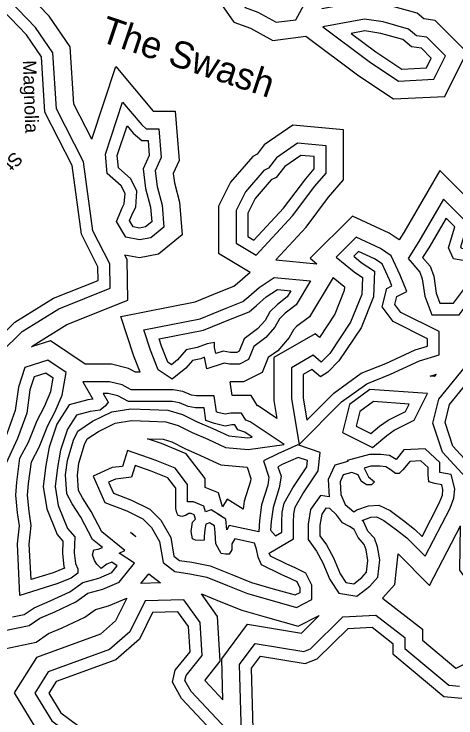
# Model space of a CAD drawing. Extents: x 2104537 to 2336408, y 34176 to 229611.
# Drawn here: x 2191069 to 2193537, y 61547 to 65482 of the extents above; entities that cross this region are included whole.
import ezdxf

# ---------------------------------------------------------------- set-up
doc = ezdxf.new("R2010")
doc.units = 0
for name, color, linetype in [('Exist Hydrographic Buffer Line', 7, 'Continuous'), ('Exist Hydrographic Island Shore', 7, 'Continuous'), ('Exist Hydrographic River Shore', 7, 'Continuous'), ('Exist Road Non-System Type 51 Label', 7, 'Continuous'), ('Old_Level_32', 7, 'Continuous')]:
    doc.layers.add(name, color=color, linetype=linetype)

msp = doc.modelspace()

# ---------------------------------------------------------------- linework, layer by layer
at = {"layer": 'Exist Hydrographic Buffer Line'}
for points in [[(2192286.8, 65662.8), (2192272, 65644.4), (2192360, 65518.6), (2192429.9, 65492.4), (2192533.9, 65436.4), (2192643.1, 65450), (2192701.1, 65556.3), (2192744.4, 65643.1), (2192694.7, 65734.2), (2192694.7, 65767.9), (2192719.5, 65836), (2192736.2, 65902.8), (2192651.7, 65987.3), (2192581.5, 66013.7), (2192494, 66040.6), (2192429.4, 66069.4), (2192355.9, 66085.1), (2192334.1, 66125.1), (2192323.3, 66184.6), (2192323.3, 66189.3), (2192364.5, 66223.7), (2192364.5, 66319.1), (2192268.3, 66376.9), (2192157.7, 66469.1)], [(2190989.7, 63585.2), (2191114.3, 63707.3), (2191319.4, 63834.1), (2191604.9, 63949), (2191603, 64084.7), (2191508.3, 64270.6), (2191456.2, 64655.5), (2191305.3, 64951.5), (2191286, 65264.7), (2191188.9, 65407.1), (2191039.9, 65563.1), (2190793.9, 65645.6), (2190364.1, 65611.5), (2190190, 65689.2), (2190098.8, 65777.5), (2189893.2, 65745.3), (2189917, 65845), (2189904, 65986.7), (2189704.4, 66111.5)], [(2191502.4, 64781.6), (2191402.3, 64978), (2191382.6, 65297.8), (2191265.7, 65469.2), (2191094.3, 65648.7), (2190806.1, 65745.3), (2190381.3, 65711.6), (2190246, 65772), (2190132, 65882.3), (2190014.1, 65863.9), (2189998, 66040)], [(2192149.7, 65649), (2192149.2, 65648.3), (2192296.8, 65437.2), (2192389.1, 65402.6), (2192514.9, 65334.8), (2192699.6, 65357.9)], [(2192699.6, 65357.9), (2192995.2, 65136.1), (2193188.5, 65007.1), (2193476, 65021.5), (2193599.1, 65268), (2193420.8, 65446.5), (2193358.9, 65454.2), (2193320.5, 65487.2), (2193152.1, 65534), (2193025.9, 65553.4), (2192788, 65510.1)], [(2192792.9, 65411), (2193052.1, 65216.5), (2193216.1, 65107), (2193413.6, 65116.9), (2193479.4, 65248.6), (2193375.1, 65353), (2193317.3, 65360.2), (2193273, 65398.2), (2193131.4, 65437.6), (2193027.2, 65453.6), (2192792.9, 65411)], [(2191502.4, 64781.6), (2191637.9, 65188.4)], [(2191637.9, 65188.4), (2191846.1, 64938.4), (2191968.3, 64938.4), (2191991.3, 64662.8), (2191958.4, 64590.4), (2191965, 64537.3), (2191993.4, 64430.8), (2192008.7, 64246.6), (2191875, 64139.5), (2191769.2, 64118.3), (2191688.1, 64134.6)], [(2191675.4, 64989.6), (2191781.7, 64861.9), (2191807.3, 64840), (2191877.8, 64840), (2191891.1, 64680.2), (2191857.3, 64605.8), (2191868.2, 64518.5), (2191896, 64413.9), (2191906.3, 64290.7), (2191832.2, 64231.3), (2191769.2, 64218.7), (2191693.5, 64233.9), (2191640.7, 64321.9), (2191675.3, 64402.7), (2191684.1, 64420.5), (2191688.6, 64479.1), (2191667.9, 64520.5), (2191589.5, 64591.2), (2191578.7, 64699.2), (2191675.4, 64989.6)], [(2192530.8, 64106.9), (2192700.3, 64290.7), (2192825.5, 64457.7), (2192910.1, 64554.5), (2192910.1, 64834.7), (2192625.9, 64860.5), (2192466.9, 64750.3), (2192426.1, 64697.9), (2192402.7, 64686.2), (2192278.3, 64542.6), (2192210.5, 64406.9), (2192210.5, 64144.6), (2192387, 64038.7)], [(2192421, 64133), (2192624.6, 64353.7), (2192748.9, 64519.7), (2192811.7, 64591.4), (2192811.7, 64744.8), (2192652.6, 64759.3), (2192535.3, 64678), (2192490.1, 64619.9), (2192464.2, 64606.9), (2192360.9, 64487.6), (2192309, 64383.7), (2192309, 64200.3), (2192421, 64133)], [(2193447.7, 64607.3), (2193245.4, 64260.3), (2193219.9, 64219.5)], [(2194159.6, 64601.1), (2193777.8, 64601.1), (2193668.6, 64431.2), (2193650.4, 64404.4), (2193447.7, 64607.3)], [(2193468.3, 64447.3), (2193329.6, 64209.4), (2193270.3, 64114.3), (2193335.3, 64038.3), (2193349.4, 64000.8), (2193363.2, 63904.4), (2193402.3, 63800.1), (2193556.2, 63800.1), (2193628.5, 63896.6), (2193698.6, 63931.6), (2193785.8, 64058.5), (2193953.1, 64365.4), (2194021.7, 64502.7), (2193831.5, 64502.7), (2193750.7, 64376.9), (2193654.2, 64235.2), (2193629.2, 64216.5), (2193596, 64176.6), (2193584.7, 64169.1), (2193569.3, 64171.9), (2193565.6, 64180.1), (2193604.2, 64311.4), (2193468.3, 64447.3)], [(2193219.9, 64219.5), (2193163.5, 64257.1), (2192958.6, 64351.7), (2192723.3, 64116.3), (2192759.4, 64086.2)], [(2192661, 63075.1), (2192898.9, 63313.1), (2193039.5, 63415.4), (2193170.9, 63468.1), (2193333.4, 63542.6), (2193444.6, 63575.9), (2193444.6, 63706.6), (2193229.6, 63814.2), (2193196, 63858.9), (2193207.7, 63902.9), (2193262.8, 63930.4), (2193226, 64022.4), (2193176.2, 64130.3), (2193115.3, 64170.9), (2192979.7, 64233.6), (2192869, 64122.9), (2192968.7, 64039.8), (2193015.8, 64009.8), (2193011.2, 63914.2), (2192949.1, 63758.7), (2192832.6, 63583.9), (2192784.4, 63535.7), (2192739.9, 63573.9), (2192618.5, 63504.5), (2192618.5, 63330.2), (2192661, 63075.1)], [(2191166.7, 63620.9), (2191175.4, 63629.3), (2191364, 63746), (2191704.2, 63882.9), (2191701.1, 64109), (2191688.1, 64134.6)], [(2192530.8, 64106.9), (2192759.4, 64086.2)], [(2191664.6, 63791.4), (2192079.7, 63872.2), (2192216.7, 63928.3), (2192296.4, 63960.1), (2192316.2, 63976.7), (2192387, 64038.7)], [(2191793.4, 63716.2), (2192108.1, 63777.4), (2192253.7, 63837), (2192347.4, 63874.6), (2192380.1, 63901.8), (2192437.8, 63952.3), (2192522.6, 64008.9), (2192725.4, 63990.4), (2192644.4, 63855.4), (2192582.8, 63809.1), (2192551, 63777.3), (2192524.8, 63731.4), (2192474.5, 63672.6), (2192407.9, 63624.1), (2192378.1, 63549.7), (2192328.2, 63524.7), (2192272.8, 63524.7), (2192242.3, 63529.8), (2192146, 63497.7), (2192132.9, 63562.9), (2192111.3, 63554.8), (2192065.9, 63544.7), (2192028, 63501.5), (2191951.6, 63440.3), (2191873.7, 63492.3), (2191831.3, 63602.6), (2191793.4, 63716.2)], [(2192851.5, 64009.4), (2192718.9, 63788.2), (2192647.5, 63734.6), (2192630, 63717.1), (2192605.6, 63674.4), (2192541.7, 63599.8), (2192488.7, 63561.3), (2192455.6, 63478.4), (2192351.4, 63426.3), (2192275.4, 63426.3)], [(2192851.5, 64009.4), (2192910.5, 63960.2), (2192914.8, 63957.4), (2192913.7, 63935.4), (2192861.5, 63804.8), (2192774.4, 63674), (2192751.3, 63693.8), (2192520.1, 63561.6), (2192520.1, 63322.1), (2192536.9, 63221)], [(2191773.1, 63479.7), (2191738.6, 63569.4), (2191664.6, 63791.4)], [(2193614.6, 62866.2), (2193461.7, 63031.8), (2193408.6, 63195.4), (2193441.6, 63329.1), (2193810.1, 63781.6)], [(2191272, 63654.1), (2191166.7, 63620.9)], [(2191466.4, 63524.5), (2191272, 63654.1)], [(2191256.6, 63546), (2191129.4, 63505.8), (2191092.7, 63395.8), (2191075.7, 63266), (2191027.5, 63134.2), (2190959.8, 62988.1), (2190940.2, 62882.1), (2190936.6, 62759), (2190936.6, 62633.3), (2190940.1, 62489), (2190953.9, 62350.7), (2190957.2, 62272.6), (2190953.1, 62167), (2191027.4, 62036.9), (2191152.4, 62063.2), (2191212.8, 62104.8), (2191297.2, 62140.5), (2191413.8, 62195.2), (2191481.3, 62243.4), (2191563.8, 62265.7), (2191655.1, 62304.8), (2191742, 62411.1), (2191656, 62468.5)], [(2191656, 62468.5), (2191688.4, 62482.4), (2191559.6, 62587.1), (2191499.3, 62701.5), (2191450.6, 62778), (2191427.9, 62818.5), (2191422.4, 62903.9), (2191431.2, 62971.4), (2191462.6, 63075.3), (2191477, 63106.1), (2191540.5, 63148.4), (2191634.4, 63193.9), (2191725.3, 63208.6), (2191825.5, 63205.3), (2191917, 63202.2), (2191985.9, 63182.1), (2192064.6, 63142.7), (2192151.6, 63104.4), (2192250.6, 63058.7), (2192376.1, 63046.5), (2192577.9, 63075.4), (2192387.2, 63202.5), (2192363.2, 63211.3), (2192338.7, 63250.5), (2192279.2, 63250.5), (2192249, 63245), (2192207.5, 63254.8), (2192200.1, 63257.4), (2192187.3, 63346.9), (2192087.7, 63346.9), (2192059.5, 63351.6), (2192011.4, 63372.2), (2191957, 63381.3), (2191910.2, 63381.3), (2191862.1, 63381.3), (2191723.6, 63381.3), (2191672.5, 63408.4), (2191601.9, 63426), (2191453.3, 63426), (2191508.9, 63328.6), (2191481.3, 63325.1), (2191377, 63296.7), (2191307, 63189.3), (2191265.1, 63059.7), (2191246.9, 62957.3), (2191231.7, 62839.6), (2191251.6, 62716.2), (2191310, 62572.1), (2191341.5, 62535.3), (2191338.9, 62466.3), (2191347.5, 62392.9), (2191351.4, 62384.2), (2191286.4, 62358.7), (2191163.4, 62319.8), (2191154, 62518.7), (2191164.6, 62621.7), (2191153.3, 62700.7), (2191143.8, 62792.8), (2191150, 62857.5), (2191165.5, 62978.6), (2191209.6, 63060.7), (2191258, 63181.6), (2191299, 63260.3), (2191337.2, 63352), (2191359.9, 63477.1), (2191256.6, 63546)], [(2191773.1, 63479.7), (2191748.1, 63479.7), (2191708, 63500.9), (2191614, 63524.5), (2191466.4, 63524.5)], [(2191014.1, 63471.4), (2190996.4, 63418), (2190979.5, 63289.6), (2190936.5, 63171.9), (2190865.3, 63018.2), (2190842, 62892.5), (2190838.1, 62760.5), (2190838.1, 62632.2), (2190841.8, 62482.9), (2190855.7, 62343.8), (2190858.7, 62272.5), (2190853.7, 62142.7), (2190977.5, 61925.8), (2191192, 61971), (2191260.3, 62018), (2191337.3, 62050.6), (2191463.8, 62109.9), (2191524.1, 62153), (2191596.1, 62172.5), (2191699.2, 62216.7)], [(2193392.6, 63457.6), (2193428, 63468.2)], [(2193417.9, 63455.8), (2193392.6, 63457.6)], [(2193417.9, 63455.8), (2193428, 63468.2)], [(2192536.9, 63221), (2192432, 63291), (2192428.8, 63292.2), (2192393.3, 63348.9), (2192286.4, 63348.9), (2192275.4, 63426.3)], [(2193072.1, 63057.8), (2193151.2, 63125.6), (2193192.8, 63155.3), (2193304, 63211), (2193378.4, 63359.9), (2193057, 63382.1), (2192942.7, 63298.9), (2192903.5, 63142.2), (2193072.1, 63057.8)], [(2192233.4, 62726.3), (2192211, 62804.7), (2192136.2, 62834.7), (2192136.2, 62885.8), (2192030.7, 63023.9), (2191892.4, 63080.3), (2191814.6, 63107.2)], [(2191814.6, 63107.2), (2191901.2, 63104.2), (2191949.8, 63090.1), (2192022.7, 63053.6), (2192111.1, 63014.7), (2192224.4, 62962.3), (2192371.1, 62948.1)], [(2191702.9, 63041.8), (2191674.7, 62952.6), (2191617.3, 62946), (2191510.9, 62897.6), (2191575.9, 62751.2), (2191698.1, 62704.8), (2191788.8, 62659.4), (2191837, 62611.2), (2191881.8, 62532.6), (2191901.3, 62415.7), (2191966.1, 62365.3), (2192050.3, 62352.7), (2192146, 62333.5), (2192260.6, 62287.6), (2192373.8, 62241.6), (2192497.8, 62206.1), (2192646.2, 62164.9), (2192732.6, 62208.1), (2192732.6, 62288.2), (2192698.7, 62356.1), (2192643.2, 62383.8), (2192588.2, 62407.9), (2192501.5, 62451.3), (2192494.6, 62467.9)], [(2192138.8, 62699.2), (2192129.6, 62731.3), (2192070.8, 62754.8), (2192037.8, 62754.8), (2192037.8, 62852.5), (2191968.7, 62942.9), (2191857.7, 62988.1), (2191702.9, 63041.8)], [(2192494.6, 62467.9), (2192629.4, 62548.8), (2192629.4, 62639), (2192632.4, 62687.6), (2192639.8, 62724.7), (2192681.6, 62799.3), (2192768.4, 62927.8), (2192778.7, 63030.9), (2192653.4, 63072.7), (2192542.7, 63024), (2192462.9, 62984), (2192493, 62893.6), (2192485.9, 62848.8), (2192451.3, 62737.8), (2192440, 62651.1), (2192435.3, 62586.2)], [(2193012.8, 62650.1), (2193062.3, 62668.3), (2193093.6, 62670.2), (2193134.9, 62649.5), (2193205.3, 62598.2), (2193263.2, 62553.2), (2193365, 62451.3), (2193504.2, 62720.1), (2193525.8, 62776.1), (2193531.5, 62827.2), (2193511.5, 62907.3), (2193448, 62918.8), (2193448, 62975.5), (2193365.1, 63051.6), (2193245.9, 63045), (2193204.2, 62991.9), (2193165.8, 63013.8), (2193117.7, 63019.2), (2193053.7, 63019.2), (2192930.2, 62985.5), (2192932.6, 62980.7), (2192860.5, 62960.1), (2192824.2, 62880.2), (2192828.8, 62783.3)], [(2192371.1, 62948.1), (2192392.1, 62885.3), (2192389.8, 62871.2), (2192354.8, 62759), (2192348.9, 62713.8)], [(2192348.9, 62713.8), (2192259.7, 62769.5), (2192233.4, 62726.3)], [(2192779.8, 62789.4), (2192725.1, 62711.2), (2192711.4, 62629.3), (2192711.4, 62543.8), (2192759, 62478.9), (2192793.3, 62413.4), (2192832.3, 62321.2), (2192882.3, 62243.4), (2192984, 62227.7), (2193055.9, 62283), (2193101.5, 62334.4), (2193111.5, 62429.9), (2193098.8, 62502.3), (2193082.6, 62551), (2193045.6, 62591.6), (2193021, 62645), (2193012.8, 62650.1)], [(2192828.8, 62783.3), (2192779.8, 62789.4)], [(2192223.6, 62676), (2192169.9, 62709.6), (2192138.8, 62699.2)], [(2192435.3, 62586.2), (2192271.2, 62622.1), (2192256.7, 62598.9), (2192251.3, 62658.7), (2192207.5, 62686.1)], [(2193127.9, 62215.9), (2193349.7, 62043.5), (2193349.7, 61980.8), (2193536.1, 61824.8), (2193538.2, 61824.7), (2193655.4, 61883.9), (2193772.3, 61848.5), (2193770.8, 62040.4), (2193756.6, 62099.4), (2193558.7, 62373.6), (2193563.1, 62619.7)], [(2193214, 62463.2), (2193390.5, 62286.6), (2193563.1, 62619.7)], [(2191749.1, 62559.9), (2191719.3, 62584.1)], [(2191719.3, 62584.1), (2191730.5, 62578.5), (2191749.1, 62559.9)], [(2193127.9, 62215.9), (2193196.1, 62292.7), (2193214, 62463.2)], [(2191777.5, 62299.1), (2191821.6, 62353)], [(2191821.6, 62353), (2191887, 62302.1)], [(2191887, 62302.1), (2191777.5, 62299.1)], [(2191699.2, 62216.7), (2191636.2, 62089.3), (2191551.7, 62015.3), (2191194.9, 61885.1), (2191069.4, 61686.8), (2191206, 61463.6), (2191224.5, 61449.7)], [(2192235.4, 61648.4), (2192138.5, 61751.8), (2192135.5, 61757.3), (2192220.5, 61863.1), (2192204.4, 62114.4), (2192115.5, 62239.7)], [(2192115.5, 62239.7), (2192223.8, 62196.3), (2192341.6, 62148.4), (2192471.1, 62111.4), (2192656.4, 62059.9), (2192774, 62118.8)], [(2192340.8, 61392), (2192058.2, 61693.5), (2192023.5, 61756.7), (2192029.9, 61783.1), (2192119.8, 61895), (2192108, 62080.2), (2192017.9, 62207.1), (2191801.5, 62201.3), (2191715.7, 62028.1), (2191602.7, 61929.2), (2191260.1, 61804.2), (2191185.4, 61685.9), (2191280.2, 61530.9), (2191444.6, 61407), (2191586.5, 61376.3), (2191674.2, 61269.3), (2191805.3, 61207.1), (2192005, 61183.6), (2192185.7, 61095.4)], [(2192235.4, 61648.4), (2192229.2, 61876.2), (2192372.2, 62070.3), (2192674.7, 62020.8), (2192774, 62118.8)], [(2192340.8, 61392), (2192328.5, 61845), (2192415.7, 61963.5), (2192688.1, 61918.9), (2192725.7, 61932.9), (2192906.2, 62111), (2193089.7, 62121), (2193251.2, 61995.4), (2193251.2, 61934.8), (2193496.8, 61729.4), (2193557.7, 61724.2)]]:
    msp.add_lwpolyline(points, dxfattribs=at)
at = {"layer": 'Exist Hydrographic Island Shore'}
for points in [[(2192952.4, 65373.3), (2193090, 65270), (2193234.5, 65173.7), (2193372.1, 65180.5), (2193399.6, 65235.6), (2193344.6, 65290.7), (2193289.5, 65297.6), (2193241.4, 65338.9), (2193117.5, 65373.3), (2193028.1, 65387.1), (2192952.4, 65373.3)], [(2191700.4, 64857), (2191734.8, 64815.7), (2191783, 64774.4), (2191817.4, 64774.4), (2191824.3, 64691.8), (2191789.9, 64616.1), (2191803.6, 64505.9), (2191831.1, 64402.7), (2191838, 64320), (2191803.6, 64292.5), (2191769.2, 64285.6), (2191734.8, 64292.5), (2191714.2, 64326.9), (2191734.8, 64375.1), (2191748.6, 64402.7), (2191755.5, 64492.1), (2191721.1, 64561), (2191652.3, 64622.9), (2191645.4, 64691.8), (2191700.4, 64857)], [(2192409, 64216.8), (2192574.1, 64395.8), (2192697.9, 64561), (2192746.1, 64616.1), (2192746.1, 64684.9), (2192670.4, 64691.8), (2192581, 64629.8), (2192532.8, 64567.9), (2192505.3, 64554.1), (2192415.9, 64450.8), (2192374.6, 64368.2), (2192374.6, 64237.4), (2192409, 64216.8)], [(2193482.1, 64340.7), (2193385.8, 64175.5), (2193351.4, 64120.4), (2193392.7, 64072.2), (2193413.3, 64017.1), (2193427.1, 63920.8), (2193447.7, 63865.7), (2193523.4, 63865.7), (2193585.3, 63948.3), (2193654.1, 63982.7), (2193729.8, 64092.9), (2193894.9, 64395.8), (2193915.5, 64437.1), (2193867.4, 64437.1), (2193805.5, 64340.7), (2193702.3, 64189.2), (2193674.8, 64168.6), (2193640.4, 64127.3), (2193599.1, 64099.8), (2193523.4, 64113.5), (2193495.9, 64175.5), (2193530.3, 64292.5), (2193482.1, 64340.7)], [(2192704.8, 63211.7), (2192856.1, 63363.2), (2193007.5, 63473.3), (2193145.1, 63528.4), (2193310.2, 63604.1), (2193379, 63624.8), (2193379, 63666.1), (2193186.3, 63762.4), (2193124.4, 63845), (2193151.9, 63948.3), (2193179.5, 63962.1), (2193165.7, 63996.5), (2193124.4, 64086), (2193083.1, 64113.5), (2192993.7, 64154.8), (2192966.2, 64127.3), (2193007.5, 64092.9), (2193083.1, 64044.7), (2193076.3, 63900.1), (2193007.5, 63728), (2192883.7, 63542.2), (2192821.7, 63480.2), (2192780.5, 63452.7), (2192732.3, 63494), (2192684.2, 63466.4), (2192684.2, 63335.6), (2192704.8, 63211.7)], [(2191879.3, 63666.1), (2192126.9, 63714.3), (2192278.3, 63776.2), (2192381.5, 63817.5), (2192422.7, 63851.9), (2192477.8, 63900.1), (2192539.7, 63941.4), (2192615.4, 63934.5), (2192594.7, 63900.1), (2192539.7, 63858.8), (2192498.4, 63817.5), (2192470.9, 63769.3), (2192429.6, 63721.1), (2192354, 63666.1), (2192326.4, 63597.2), (2192312.7, 63590.3), (2192278.3, 63590.3), (2192237, 63597.2), (2192195.7, 63583.5), (2192188.9, 63617.9), (2192188.9, 63645.4), (2192147.6, 63638.5), (2192092.5, 63617.9), (2192030.6, 63604.1), (2191982.5, 63549), (2191948.1, 63521.5), (2191927.4, 63535.3), (2191893, 63624.8), (2191879.3, 63666.1)], [(2191246.4, 63474), (2191181.1, 63453.3), (2191157, 63381.1), (2191139.8, 63250.3), (2191088.2, 63109.1), (2191022.8, 62968)], [(2191514.7, 62486.1), (2191538.8, 62489.6), (2191562.8, 62499.9), (2191507.8, 62544.7), (2191442.5, 62668.6), (2191394.3, 62744.3), (2191363.3, 62799.4), (2191356.5, 62906.1), (2191366.8, 62985.2), (2191401.2, 63098.8), (2191425.3, 63150.5), (2191507.8, 63205.5), (2191614.4, 63257.2), (2191721.1, 63274.4), (2191827.7, 63270.9), (2191927.4, 63267.5), (2192010, 63243.4), (2192092.5, 63202.1), (2192178.5, 63164.2), (2192268, 63122.9), (2192374.6, 63112.6), (2192398.7, 63116), (2192357.4, 63143.6), (2192319.6, 63157.3), (2192302.4, 63184.9), (2192285.2, 63184.9), (2192247.3, 63178), (2192188.9, 63191.8), (2192140.7, 63209), (2192130.4, 63281.2), (2192082.2, 63281.2), (2192040.9, 63288.1), (2191992.8, 63308.8), (2191951.5, 63315.7), (2191910.2, 63315.7), (2191862.1, 63315.7), (2191707.3, 63315.7), (2191648.8, 63346.6), (2191593.8, 63360.4), (2191566.3, 63360.4), (2191593.8, 63312.2), (2191580, 63291.6), (2191549.1, 63267.5), (2191494.1, 63260.6), (2191418.4, 63239.9), (2191366.8, 63160.8), (2191329, 63043.7), (2191311.8, 62947.4), (2191298, 62840.7), (2191315.2, 62734), (2191366.8, 62606.6), (2191408.1, 62558.4), (2191404.6, 62468.9), (2191411.5, 62410.4), (2191425.3, 62379.4), (2191425.3, 62355.3), (2191387.4, 62327.8), (2191308.3, 62296.8), (2191101.9, 62231.4), (2191088.2, 62520.6), (2191098.5, 62620.4), (2191088.2, 62692.7), (2191077.9, 62792.5), (2191084.7, 62864.8), (2191101.9, 62999), (2191150.1, 63088.5), (2191198.2, 63209), (2191239.5, 63288.1), (2191273.9, 63370.7), (2191287.7, 63446.5), (2191246.4, 63474)], [(2193062.5, 63136), (2193110.7, 63177.3), (2193158.8, 63211.7), (2193255.1, 63259.9), (2193275.8, 63301.2), (2193076.3, 63315), (2193000.6, 63259.9), (2192980, 63177.3), (2193062.5, 63136)], [(2192529.4, 62565.3), (2192563.8, 62586), (2192563.8, 62641), (2192567.2, 62696.1), (2192577.5, 62747.7), (2192625.7, 62833.8), (2192704.8, 62950.8), (2192708.2, 62985.2), (2192656.6, 63002.4), (2192570.6, 62964.6), (2192543.1, 62950.8), (2192560.3, 62899.2), (2192550, 62833.8), (2192515.6, 62723.6), (2192505.3, 62644.5), (2192501.9, 62596.3), (2192529.4, 62565.3)], [(2192983.4, 62709.2), (2193048.8, 62733.3), (2193107.2, 62736.7), (2193169.1, 62705.7), (2193244.8, 62650.7), (2193306.7, 62602.5), (2193348, 62561.2), (2193444.3, 62747), (2193461.5, 62791.8), (2193464.9, 62822.8), (2193458.1, 62850.3), (2193420.2, 62857.2), (2193385.8, 62867.5), (2193382.4, 62905.4), (2193382.4, 62946.7), (2193341.1, 62984.5), (2193279.2, 62981.1), (2193241.4, 62932.9), (2193220.7, 62912.3), (2193200.1, 62912.3), (2193169.1, 62936.4), (2193145.1, 62950.1), (2193114.1, 62953.6), (2193062.5, 62953.6), (2193024.7, 62943.2), (2193048.8, 62895.1), (2193083.1, 62867.5), (2193065.9, 62850.3), (2193038.4, 62850.3), (2193007.5, 62871), (2192990.3, 62905.4), (2192955.9, 62919.1), (2192907.7, 62905.4), (2192890.5, 62867.5), (2192894, 62795.2), (2192918, 62740.2), (2192966.2, 62698.9), (2192983.4, 62709.2)], [(2191745.1, 62957.7), (2191724.5, 62892.3), (2191635.1, 62882), (2191597.2, 62864.8), (2191624.8, 62802.8), (2191724.5, 62764.9), (2191827.7, 62713.3), (2191889.6, 62651.4), (2191944.6, 62555), (2191961.8, 62451.7), (2191992.8, 62427.6), (2192061.6, 62417.3), (2192164.8, 62396.7), (2192285.2, 62348.5), (2192395.2, 62303.7), (2192515.6, 62269.3), (2192639.4, 62234.9), (2192667, 62248.6), (2192667, 62272.7), (2192649.8, 62307.2), (2192615.4, 62324.4), (2192560.3, 62348.5), (2192450.3, 62403.5), (2192433.1, 62444.8), (2192422.7, 62489.6), (2192412.4, 62524), (2192302.4, 62548.1), (2192285.2, 62520.6), (2192285.2, 62486.1), (2192271.4, 62462.1), (2192250.8, 62462.1), (2192226.7, 62465.5), (2192195.7, 62520.6), (2192192.3, 62582.5), (2192188.9, 62620.4)], [(2192140.7, 62630.7), (2192133.8, 62599.7), (2192130.4, 62561.9), (2192130.4, 62541.2), (2192109.7, 62537.8), (2192082.2, 62541.2), (2192065, 62548.1), (2192058.1, 62589.4), (2192065, 62641), (2192082.2, 62658.2), (2192075.3, 62682.3), (2192058.1, 62689.2), (2192044.4, 62689.2), (2192027.2, 62678.9), (2192006.6, 62672), (2191985.9, 62678.9), (2191979, 62692.7), (2191972.2, 62716.8), (2191972.2, 62754.6), (2191972.2, 62830.3), (2191927.4, 62888.9), (2191834.6, 62926.7), (2191745.1, 62957.7)], [(2192810.9, 62719.4), (2192787.3, 62685.8), (2192777, 62623.8), (2192777, 62565.3), (2192814.9, 62513.7), (2192852.7, 62441.4), (2192890.5, 62351.9), (2192921.5, 62303.7), (2192966.2, 62296.8), (2193010.9, 62331.3), (2193038.4, 62362.2), (2193045.3, 62427.6), (2193035, 62486.1), (2193024.7, 62517.1), (2192990.3, 62555), (2192969.6, 62599.7), (2192942.1, 62616.9), (2192904.3, 62637.6), (2192869.9, 62682.3), (2192832.1, 62716.8), (2192810.9, 62719.4)], [(2192188.9, 62620.4), (2192161.3, 62637.6), (2192140.7, 62630.7)], [(2191556, 62382.9), (2191531.9, 62407), (2191518.1, 62427.6), (2191507.8, 62458.6), (2191514.7, 62486.1)], [(2191060.7, 62111), (2191126, 62124.7), (2191181.1, 62162.6), (2191270.5, 62200.5), (2191380.5, 62252.1), (2191452.8, 62303.7), (2191542.2, 62327.8), (2191614.4, 62358.8), (2191645.4, 62396.7), (2191614.4, 62417.3), (2191586.9, 62407), (2191556, 62382.9)], [(2192191.7, 61165.5), (2192307.8, 61199.3), (2192314.8, 61323.9), (2192004.7, 61654.7), (2191953.7, 61747.5), (2191969.7, 61812.8), (2192052.7, 61916.2), (2192043.7, 62057.4), (2191984.6, 62140.6), (2191842.7, 62136.8), (2191768.7, 61987.3), (2191636.7, 61871.7), (2191303.6, 61750.2), (2191262.6, 61685.4), (2191329.7, 61575.8), (2191472.6, 61468.1), (2191622.7, 61435.6), (2191715.6, 61322.3), (2191823.7, 61271), (2192023.8, 61247.4), (2192191.7, 61165.5)]]:
    msp.add_lwpolyline(points, dxfattribs=at)
at = {"layer": 'Exist Hydrographic River Shore'}
for points in [[(2190943.7, 63632), (2191073.6, 63759.2), (2191289.7, 63892.9), (2191538.6, 63993.1), (2191537.6, 64068.5), (2191444.7, 64250.8), (2191392.6, 64635.6), (2191240.7, 64933.9), (2191221.6, 65242.6), (2191137.8, 65365.6), (2191003.7, 65506), (2190785.7, 65579.1), (2190352.6, 65544.8), (2190152.7, 65634), (2190076.6, 65707.6), (2189852.7, 65672.6), (2189818.7, 65715.9), (2189850.6, 65849.8), (2189841.6, 65948.4), (2189684.6, 66046.5)], [(2193670.8, 62902.1), (2193519.6, 63065.8), (2193476.8, 63197.8), (2193501.8, 63299.1), (2193864.7, 63744.8)], [(2192405.8, 61417.3), (2192394.7, 61824.3), (2192444.8, 61892.2), (2192694.7, 61851.3), (2192761.8, 61876.3), (2192934.6, 62046.8), (2193068.7, 62054.1), (2193185.6, 61963.3), (2193185.6, 61904.2), (2193470.6, 61665.8), (2193570.7, 61657.3)]]:
    msp.add_lwpolyline(points, dxfattribs=at)

# ---------------------------------------------------------------- texts
at = {"layer": 'Exist Road Non-System Type 51 Label'}
for s, rotation, p in [('Magnolia', 272.0292, (2191117.4, 65222.1)), ('St.', 227.2438, (2191069.4, 64717.8))]:
    msp.add_text(s, height=75, rotation=rotation, dxfattribs=at).set_placement(p)
at = {"layer": 'Old_Level_32'}
msp.add_text('The Swash', height=150, rotation=341.4631, dxfattribs=at).set_placement((2191540.9, 65331.1))

doc.saveas('drawing.dxf')
